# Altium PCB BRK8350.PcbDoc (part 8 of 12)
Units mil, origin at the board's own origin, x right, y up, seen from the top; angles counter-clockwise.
Board outline 9448.82 x 5905.51 mil, 8 copper layers (L1-TOP, L2-GND, L3-SIG, L4-GND, L5-PWR, L6-PWR, L7-GND, L8-BOT), stack 57.69 mil thick; 288 components, 543 nets, 1891 pads, 2032 vias.
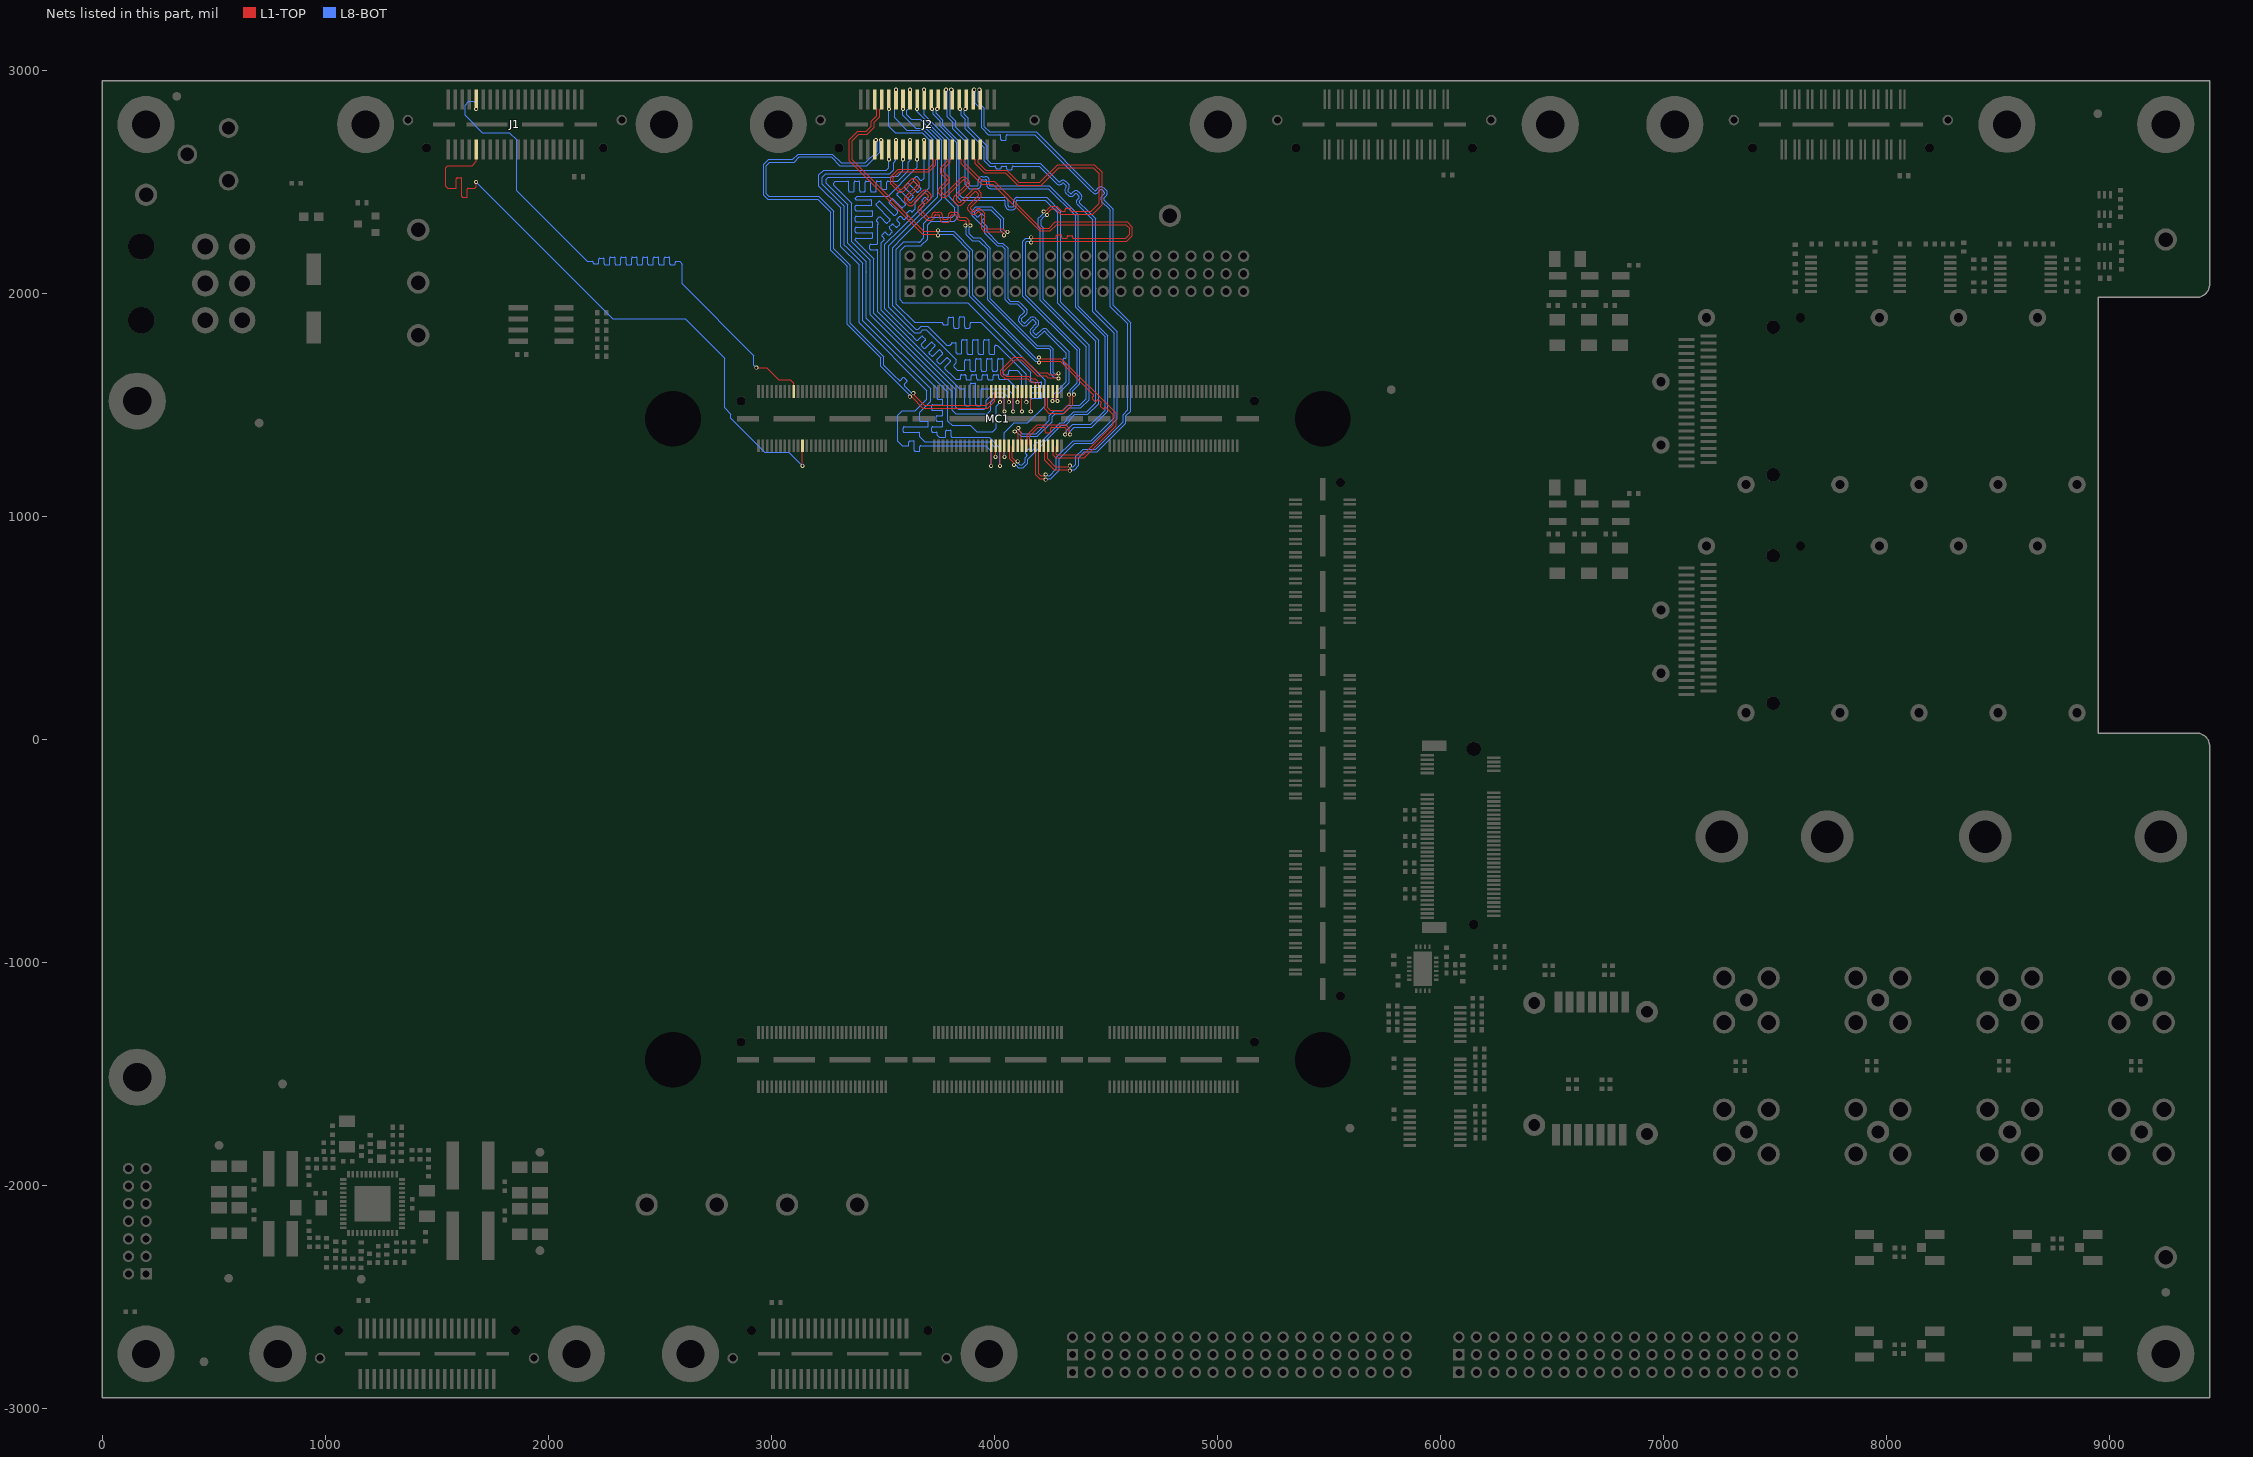
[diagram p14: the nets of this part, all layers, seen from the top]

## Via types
v1: diameter 18, hole 10, L1-TOP to L8-BOT, tented both sides, 2032 vias

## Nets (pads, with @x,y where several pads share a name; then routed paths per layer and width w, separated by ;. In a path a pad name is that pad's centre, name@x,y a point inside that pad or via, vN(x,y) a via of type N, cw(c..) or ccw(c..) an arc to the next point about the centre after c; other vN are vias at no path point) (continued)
PORTC_S26: J1.31 MC1.17 | length 2790.1
  L1-TOP w4.5: v1(2933.07,1665.35) 2978.96,1665.35 3032.81,1611.5 3085.36,1611.5 3100.41,1596.46 MC1.17@3100.41,1558.68
  L8-BOT w4.5: v1(1677.14,2825.35) 1677.14,2848.59 1666.48,2859.25 1644.69,2859.25 1626.97,2841.54 1626.97,2797.24 1705.16,2719.05 1826.22,2719.05 1858.5,2686.78 1858.5,2458.35 2175.12,2141.73 2182.98,2141.73 2197.29,2141.73 cw(c2197.29,2136.83) 2202.19,2136.83 ccw(c2207.09,2136.83) 2207.09,2131.93 2221.79,2131.93 ccw(c2221.79,2136.83) 2226.69,2136.83 2226.69,2151.87 cw(c2231.59,2151.87) 2231.59,2156.77 2246.29,2156.77 cw(c2246.29,2151.87) 2251.19,2151.87 2251.19,2130.99 ccw(c2256.09,2130.99) 2256.09,2126.09 2270.79,2126.09 ccw(c2270.79,2130.99) 2275.69,2130.99 2275.69,2156.75 cw(c2280.59,2156.75) 2280.59,2161.65 2295.29,2161.65 cw(c2295.29,2156.75) 2300.19,2156.75 2300.19,2130.99 ccw(c2305.09,2130.99) 2305.09,2126.09 2319.79,2126.09 ccw(c2319.79,2130.99) 2324.69,2130.99 2324.69,2156.75 cw(c2329.59,2156.75) 2329.59,2161.65 2344.29,2161.65 cw(c2344.29,2156.75) 2349.19,2156.75 2349.19,2130.99 ccw(c2354.09,2130.99) 2354.09,2126.09 2368.79,2126.09 ccw(c2368.79,2130.99) 2373.69,2130.99 2373.69,2156.75 cw(c2378.59,2156.75) 2378.59,2161.65 2393.29,2161.65 cw(c2393.29,2156.75) 2398.19,2156.75 2398.19,2130.99 ccw(c2403.09,2130.99) 2403.09,2126.09 2417.79,2126.09 ccw(c2417.79,2130.99) 2422.69,2130.99 2422.69,2156.75 cw(c2427.59,2156.75) 2427.59,2161.65 2442.29,2161.65 cw(c2442.29,2156.75) 2447.19,2156.75 2447.19,2130.99 ccw(c2452.09,2130.99) 2452.09,2126.09 2466.79,2126.09 ccw(c2466.79,2130.99) 2471.69,2130.99 2471.69,2156.75 cw(c2476.59,2156.75) 2476.59,2161.65 2491.29,2161.65 cw(c2491.29,2156.75) 2496.19,2156.75 2496.19,2130.99 ccw(c2501.09,2130.99) 2501.09,2126.09 2515.79,2126.09 ccw(c2515.79,2130.99) 2520.69,2130.99 2520.69,2156.75 cw(c2525.59,2156.75) 2525.59,2161.65 2540.29,2161.65 cw(c2540.29,2156.75) 2545.19,2156.75 2545.19,2130.99 ccw(c2550.09,2130.99) 2550.09,2126.09 2564.79,2126.09 ccw(c2564.79,2130.99) 2569.69,2130.99 2569.69,2136.83 cw(c2574.59,2136.83) 2574.59,2141.73 2576.84,2141.73 2589.57,2141.73 2601.38,2129.92 2601.38,2040.78 2922.49,1719.67 2922.49,1675.94 v1(2933.07,1665.35)
PORTC_S27: J1.32 MC1.22 | length 2833.7
  L1-TOP w4.5: v1(1677.14,2497.41) 1677.14,2476.36 1670.28,2469.49 1644.68,2469.49 1642.43,2469.49 ccw(c1642.43,2464.59) 1637.53,2464.59 1637.53,2433.62 cw(c1632.63,2433.62) 1632.63,2428.72 1617.93,2428.72 cw(c1617.93,2433.62) 1613.03,2433.62 1613.03,2512.09 ccw(c1608.13,2512.09) 1608.13,2516.99 1593.43,2516.99 ccw(c1593.43,2512.09) 1588.53,2512.09 1588.53,2474.39 cw(c1583.63,2474.39) 1583.63,2469.49 1553.18,2469.49 1550.2,2469.49 1540.47,2479.22 1540.47,2561.89 1550.43,2571.85 1658.46,2571.85 1677.19,2590.58 J1.32@1677.19,2643.11 ; v1(3139.61,1225.72) 3139.78,1225.88 MC1.22@3139.78,1315.37 MC1.22@3139.94,1315.53
  L8-BOT w4.5: v1(1677.14,2497.41) 2289.49,1885.07 2614.93,1885.07 2791.34,1708.66 2791.34,1484.83 2819.19,1456.98 2819.19,1438.06 2969.84,1287.4 3077.93,1287.4 v1(3139.61,1225.72)
PORTD_C2P_CLKN: J2.36 MC1.89 | length 2523.8
  L1-TOP w4.2: v1(3620.93,1535.35) 3621.89,1534.4 3628.89,1534.4 3679.82,1483.46 3970.06,1483.46 4002.38,1515.78 4002.38,1555.13 MC1.89@4005.92,1558.68
  L8-BOT w4.2: v1(3468.85,2686.46) 3468.85,2682.73 3474.09,2677.49 3474.09,2635.55 3422,2583.47 3313.12,2583.47 3273.75,2622.84 3120.83,2622.84 3097.21,2599.21 2988.01,2599.21 2965.59,2576.79 2965.59,2439.5 2983.83,2421.26 3208.66,2421.26 3267.72,2362.2 3267.72,2192.91 3341.18,2119.45 3341.18,1859.39 3491.34,1709.23 3491.34,1671.95 3540.3,1622.98 3618.29,1544.99 3618.29,1537.99 v1(3620.93,1535.35)
PORTD_C2P_CLKP: J2.34 MC1.87 | length 2523.8
  L1-TOP w4.2: v1(3636.84,1551.26) 3637.8,1550.31 3637.8,1543.31 3685.04,1496.06 3964.85,1496.06 3989.78,1521 3989.78,1555.13 MC1.87@3986.24,1558.68
  L8-BOT w4.2: v1(3491.92,2686.46) 3491.92,2682.73 3486.69,2677.49 3486.69,2630.33 3427.22,2570.87 3307.9,2570.87 3268.53,2610.24 3126.05,2610.24 3102.43,2586.61 2993.23,2586.61 2978.19,2571.57 2978.19,2444.72 2989.04,2433.86 3213.88,2433.86 3280.32,2367.42 3280.32,2198.13 3353.78,2124.67 3353.78,1864.61 3503.94,1714.45 3503.94,1677.17 3549.21,1631.89 3572.7,1608.41 ccw(c3576.12,1611.83) 3579.54,1608.41 3590.4,1619.26 cw(c3593.82,1615.84) 3597.24,1619.26 3607.51,1609 cw(c3604.09,1605.57) 3607.51,1602.15 3596.65,1591.29 ccw(c3600.08,1587.87) 3596.65,1584.45 3615.25,1565.85 3627.2,1553.9 3634.2,1553.9 v1(3636.84,1551.26)
PORTD_P2C_CLKN: J2.35 MC1.118 | length 2571.4
  L1-TOP w4.2: J2.35@3464.59,2868.71 3464.59,2831.96 3470.49,2826.06 3471.58,2826.06 3474.04,2823.6 3474.04,2796.02 3448.79,2770.77 3448.79,2748.18 3425.3,2724.69 3387.84,2724.69 3350.39,2687.25 3350.39,2592.42 3679.03,2263.78 3739.35,2263.78 3744.3,2258.83 v1(3748.03,2258.83) ; v1(4200.79,1688.63) 4203.03,1688.63 4207.98,1693.58 4294.61,1693.58 4425.68,1562.51 4444.28,1543.91 cw(c4440.86,1540.49) 4444.28,1537.06 4440.02,1532.8 ccw(c4443.44,1529.38) 4440.02,1525.96 4450.29,1515.69 ccw(c4453.71,1519.11) 4457.13,1515.69 4461.39,1519.95 cw(c4464.82,1516.53) 4468.24,1519.95 4478.51,1509.68 cw(c4475.08,1506.26) 4478.51,1502.84 4475.9,1500.24 ccw(c4479.33,1496.82) 4475.9,1493.39 4486.17,1483.13 ccw(c4489.59,1486.55) 4493.02,1483.13 4495.62,1485.73 cw(c4499.04,1482.3) 4502.46,1485.73 4520.77,1467.42 4533.03,1455.16 4533.03,1409.98 4397.86,1274.81 4280.43,1274.81 4277.97,1277.27 4277.97,1311.83 MC1.118@4281.51,1315.37
  L8-BOT w4.2: v1(3748.03,2258.83) 3751.77,2258.83 3756.72,2263.78 3812.8,2263.78 3890.96,2185.62 3890.96,2073.07 3890.96,1985.68 4182.73,1693.91 4191.77,1693.91 4197.05,1688.63 v1(4200.79,1688.63)
PORTD_P2C_CLKP: J2.33 MC1.116 | length 2571.3
  L1-TOP w4.2: J2.33@3496.09,2868.71 3496.09,2831.96 3490.19,2826.06 3489.1,2826.06 3486.64,2823.6 3486.64,2790.8 3461.39,2765.55 3461.39,2742.96 3430.52,2712.09 3393.06,2712.09 3362.99,2682.03 3362.99,2597.64 3684.25,2276.38 3739.35,2276.38 3744.3,2281.33 v1(3748.03,2281.33) ; v1(4200.79,1711.13) 4203.03,1711.13 4207.98,1706.18 4299.82,1706.18 4545.63,1460.38 4545.63,1404.76 4403.08,1262.21 4275.21,1262.21 4265.37,1272.05 4265.37,1311.83 MC1.116@4261.83,1315.37
  L8-BOT w4.2: v1(3748.03,2281.33) 3751.77,2281.33 3756.72,2276.38 3818.01,2276.38 3903.56,2190.84 3903.56,2067.85 3903.56,1990.9 4187.95,1706.51 4192.43,1706.51 4197.05,1711.13 v1(4200.79,1711.13)
PORTD_S0_D0P: J2.5 MC1.112 | length 2525.9
  L1-TOP w4.2: MC1.112@4222.46,1315.37 4226,1311.83 4226,1251.32 4268.66,1208.66 4330.71,1208.66 4335.66,1203.71 v1(4338.58,1203.71)
  L8-BOT w4.2: v1(3932.92,2912.06) 3932.92,2908.33 3927.69,2903.09 3927.69,2857.18 3955.54,2829.33 3955.54,2745.34 3978.61,2722.27 4187.18,2722.27 4443.29,2466.16 4449.23,2460.22 ccw(c4452.65,2463.64) 4456.07,2460.22 4467.06,2471.21 cw(c4479.4,2458.88) 4489.55,2473.06 4489.88,2473.06 4491.7,2471.23 4502,2460.94 4503.84,2459.1 4503.84,2458.77 cw(c4489.66,2448.61) 4502,2436.28 4491,2425.29 ccw(c4494.43,2421.87) 4491,2418.44 4520.88,2388.57 4533.48,2375.97 4533.48,1944.97 4611.03,1867.42 4611.03,1471.16 4590.03,1450.16 4590.03,1417.07 4460.97,1288 4403.99,1288 4378.19,1262.21 4378.19,1227.31 4359.55,1208.66 4347.27,1208.66 4342.32,1203.71 v1(4338.58,1203.71)
PORTD_S1_D1P: J2.6 MC1.100 | length 2569.2
  L1-TOP w4.2: J2.6@3937.09,2643.11 3937.09,2606.36 3931.19,2600.46 3930.1,2600.46 3927.64,2598 3927.64,2584.17 3960.63,2551.18 4055.12,2551.18 4110.24,2496.06 4204.72,2496.06 4284.25,2575.59 4449.1,2575.59 4483.63,2541.07 4483.63,2396.77 4440.4,2353.54 4374.02,2353.54 4297.52,2353.54 4273.9,2377.16 4257.7,2377.16 4244.39,2363.86 4239.72,2359.18 4239.72,2352.18 v1(4237.08,2349.54) ; v1(4091.61,1379.3) 4093.7,1377.21 4100.7,1377.21 4107.89,1370.02 4107.89,1318.91 MC1.100@4104.35,1315.37
  L8-BOT w4.2: v1(4091.61,1379.3) 4094.26,1376.66 4101.26,1376.66 4120.43,1357.48 4193.41,1357.48 4259.84,1423.91 4259.84,1444.98 4273.56,1458.7 4309.49,1458.7 4335.58,1484.79 4388.44,1484.79 4425.56,1521.91 4425.56,1633.42 4425.56,1765.21 4218.36,1972.4 4218.36,1988.96 4218.52,1989.11 4218.52,2216.54 4218.52,2293.68 4210.24,2301.96 4210.24,2329.7 4222.08,2341.55 4227.43,2346.9 4234.44,2346.9 v1(4237.08,2349.54)
PORTD_S2_D0N: J2.7 MC1.114 | length 2525.7
  L1-TOP w4.2: MC1.114@4242.14,1315.37 4238.6,1311.83 4238.6,1256.54 4273.88,1221.26 4330.71,1221.26 4335.66,1226.21 v1(4338.58,1226.21)
  L8-BOT w4.2: v1(3909.85,2912.06) 3909.85,2908.33 3915.09,2903.09 3915.09,2851.96 3942.94,2824.11 3942.94,2740.12 3973.39,2709.67 3995.72,2709.67 4024.38,2709.67 cw(c4024.38,2704.83) 4029.22,2704.83 4029.22,2689.48 ccw(c4034.06,2689.48) 4034.06,2684.64 4048.58,2684.64 ccw(c4048.58,2689.48) 4053.42,2689.48 4053.42,2704.83 cw(c4058.26,2704.83) 4058.26,2709.67 4060.36,2709.67 4181.96,2709.67 4434.38,2457.25 4440.32,2451.31 ccw(c4452.65,2463.64) 4464.98,2451.31 4475.97,2462.3 cw(c4479.4,2458.88) 4482.84,2462.28 ; v1(4338.58,1226.21) 4342.32,1226.21 4347.27,1221.26 4354.33,1221.26 4365.59,1232.53 4365.59,1267.43 4398.77,1300.6 4455.75,1300.6 4577.43,1422.29 4577.43,1455.38 4598.43,1476.38 4598.43,1862.2 4520.88,1939.75 4520.88,2370.75 4511.97,2379.66 4482.1,2409.53 cw(c4494.43,2421.87) 4482.1,2434.2 4493.09,2445.19 ccw(c4489.66,2448.61) 4493.07,2452.05 4482.85,2462.27
PORTD_S3_D1N: J2.8 MC1.102 | length 2569.2
  L1-TOP w4.2: J2.8@3905.59,2643.11 3905.59,2606.36 3911.49,2600.46 3912.58,2600.46 3915.04,2598 3915.04,2578.95 3955.41,2538.58 4049.9,2538.58 4105.02,2483.46 4209.94,2483.46 4289.47,2562.99 4443.88,2562.99 4471.03,2535.85 4471.03,2401.99 4435.18,2366.14 4374.02,2366.14 4347.89,2366.14 cw(c4347.89,2370.98) 4343.05,2370.98 4343.05,2375.89 ccw(c4338.21,2375.89) 4338.21,2380.73 4323.69,2380.73 ccw(c4323.69,2375.89) 4318.85,2375.89 4318.85,2370.98 cw(c4314.01,2370.98) 4314.01,2366.14 4311.91,2366.14 4302.74,2366.14 4279.12,2389.76 4252.48,2389.76 4239.18,2376.46 4230.81,2368.09 4223.81,2368.09 v1(4221.17,2365.45) ; v1(4107.52,1395.21) 4109.61,1393.12 4109.61,1386.12 4120.49,1375.24 4120.49,1318.91 MC1.102@4124.03,1315.37
  L8-BOT w4.2: v1(4107.52,1395.21) 4110.17,1392.57 4110.17,1385.57 4125.65,1370.08 4188.19,1370.08 4247.24,1429.13 4247.24,1450.2 4268.34,1471.3 4304.27,1471.3 4330.36,1497.39 4383.22,1497.39 4412.96,1527.13 4412.96,1633.42 4412.96,1759.99 4205.76,1967.18 4205.76,1994.18 4205.92,1994.33 4205.92,2216.54 4205.92,2288.46 4197.64,2296.74 4197.64,2334.92 4209.48,2346.76 4218.53,2355.81 4218.53,2362.81 v1(4221.17,2365.45)
PORTD_S4_D2P: J2.9 MC1.108 | length 2525.7
  L1-TOP w4.2: MC1.108@4183.09,1315.37 4186.63,1311.83 4186.63,1185.32 4203.44,1168.5 4224.41,1168.5 4229.36,1163.55 v1(4230.43,1163.55)
  L8-BOT w4.2: v1(3869.82,2825.35) 3869.82,2821.61 3864.59,2816.38 3864.59,2801.72 3882.62,2783.69 3882.62,2742.52 3967.5,2657.63 3967.5,2598.41 3984.24,2581.67 4205.73,2581.67 4237.7,2549.7 4288.1,2499.3 ccw(c4291.52,2502.73) 4294.94,2499.3 4296.01,2500.37 cw(c4308.35,2488.04) 4318.5,2502.22 4318.83,2502.22 4320.65,2500.4 ; v1(4230.43,1163.55) 4234.16,1163.55 4239.11,1168.5 4253.46,1168.5 4291.34,1206.38 4291.34,1257.77 4359.55,1325.98 4440.08,1325.98 4522.42,1408.32 4522.79,1408.32 4551.18,1436.72 4551.18,1635.53 4551.26,1635.61 4551.26,1648.18 4551.26,1825.85 4454.55,1922.55 4454.55,1995.14 4454.74,1995.32 4454.74,2020.43 4454.55,2020.61 4454.55,2073.88 4454.74,2074.06 4454.74,2099.17 4454.55,2099.35 4454.55,2152.62 4454.74,2152.8 4454.74,2177.91 4454.55,2178.09 4454.55,2332.85 4413.88,2373.52 4381.92,2405.49 cw(c4385.34,2408.91) 4381.92,2412.33 4388.12,2418.54 ; 4320.68,2500.37 4330.94,2490.11 ; 4330.97,2490.08 4332.79,2488.26 4332.79,2487.93 cw(c4318.61,2477.78) 4330.94,2465.44 4329.87,2464.37 ccw(c4333.3,2460.95) 4329.87,2457.53 4340.14,2447.26 ccw(c4343.56,2450.68) 4346.96,2447.24 4353.22,2453.49 cw(c4365.55,2441.16) 4375.71,2455.34 4376.04,2455.34 4377.86,2453.52 ; 4377.88,2453.49 4388.15,2443.23 4390,2441.38 4390,2441.05 cw(c4375.82,2430.9) 4388.15,2418.56
PORTD_S5_D3P: J2.10 MC1.111 | length 2569.1
  L1-TOP w4.2: J2.10@3874.09,2643.11 3874.09,2606.36 3868.19,2600.46 3867.1,2600.46 3864.64,2598 3864.64,2584.18 3896.65,2552.17 3948.03,2500.79 3998.93,2500.79 4208.38,2291.34 4245.96,2291.34 4274.31,2319.69 4595.29,2319.69 4619.42,2295.55 4619.42,2257.56 4594.15,2232.28 4381.89,2232.28 4174.06,2232.28 4169.11,2227.33 v1(4165.38,2227.33) ; MC1.111@4222.46,1558.68 4226,1555.13 4226,1480.47 4244.55,1461.91 4314.38,1461.91 4352.17,1499.7 4352.17,1535.61 4357.12,1540.56 v1(4357.12,1544.29)
  L8-BOT w4.2: v1(4165.38,2227.33) 4161.64,2227.33 4156.69,2232.28 4146.33,2232.28 4140.34,2226.29 4140.34,1991.17 4383.66,1747.85 4383.66,1593.34 4352.17,1561.85 4352.17,1552.98 4357.12,1548.03 v1(4357.12,1544.29)
PORTD_S6_D2N: J2.11 MC1.110 | length 2525.3
  L1-TOP w4.2: MC1.110@4202.77,1315.37 4199.23,1311.83 4199.23,1190.53 4208.66,1181.1 4224.41,1181.1 4229.36,1186.05 v1(4230.43,1186.05)
  L8-BOT w4.2: v1(3846.75,2825.35) 3846.75,2821.61 3851.99,2816.38 3851.99,2796.5 3870.02,2778.47 3870.02,2737.3 3954.9,2652.42 3954.9,2593.19 3979.02,2569.07 3988.78,2569.07 4002.23,2569.07 cw(c4002.23,2564.23) 4007.07,2564.23 4007.07,2561.62 ccw(c4011.91,2561.62) 4011.91,2556.78 4026.43,2556.78 ccw(c4026.43,2561.62) 4031.27,2561.62 4031.27,2564.23 cw(c4036.11,2564.23) 4036.11,2569.07 4050.63,2569.07 cw(c4050.63,2564.23) 4055.47,2564.23 4055.47,2557.01 ccw(c4060.31,2557.01) 4060.31,2552.17 4074.83,2552.17 ccw(c4074.83,2557.01) 4079.67,2557.01 4079.67,2564.23 cw(c4084.51,2564.23) 4084.51,2569.07 4086.61,2569.07 4200.51,2569.07 4228.79,2540.8 4279.19,2490.39 ccw(c4291.52,2502.73) 4303.85,2490.39 4304.92,2491.46 cw(c4308.35,2488.04) 4311.79,2491.45 ; v1(4230.43,1186.05) 4234.16,1186.05 4239.11,1181.1 4248.25,1181.1 4278.74,1211.6 4278.74,1262.99 4354.33,1338.58 4434.86,1338.58 4517.2,1420.92 4517.57,1420.92 4538.58,1441.94 4538.58,1641.82 4538.63,1641.87 4538.63,1648.16 ; 4311.8,2491.43 4322,2481.23 cw(c4318.61,2477.78) 4322.04,2474.35 4320.96,2473.28 ccw(c4333.3,2460.95) 4320.96,2448.62 4331.23,2438.35 ccw(c4343.56,2450.68) 4355.9,2438.35 4362.13,2444.59 cw(c4365.55,2441.16) 4368.99,2444.57 4379.21,2434.35 ; 4379.22,2434.34 cw(c4375.82,2430.9) 4379.26,2427.5 4373.01,2421.24 ccw(c4385.34,2408.91) 4373.01,2396.58 4404.97,2364.61 4441.95,2327.63 4441.95,2171.88 4442.14,2171.7 4442.14,2159.01 4441.95,2158.82 4441.95,2093.14 4442.14,2092.96 4442.14,2080.27 4441.95,2080.08 4441.95,2014.4 4442.14,2014.22 4442.14,2001.53 4441.95,2001.34 4441.95,1917.33 4538.66,1820.63 4538.66,1648.18
PORTD_S7_D3N: J2.12 MC1.113 | length 2569.1
  L1-TOP w4.2: J2.12@3842.59,2643.11 3842.59,2606.36 3848.49,2600.46 3849.58,2600.46 3852.04,2598 3852.04,2578.96 3878.83,2552.17 3942.81,2488.19 3993.71,2488.19 4203.16,2278.74 4251.18,2278.74 4279.53,2307.09 4590.07,2307.09 4606.82,2290.33 4606.82,2262.78 4588.93,2244.88 4381.89,2244.88 4356.03,2244.88 cw(c4356.03,2249.72) 4351.19,2249.72 4351.19,2253.12 ccw(c4346.35,2253.12) 4346.35,2257.96 4331.83,2257.96 ccw(c4331.83,2253.12) 4326.99,2253.12 4326.99,2249.72 cw(c4322.15,2249.72) 4322.15,2244.88 4307.63,2244.88 cw(c4307.63,2249.72) 4302.79,2249.72 4302.79,2256.15 ccw(c4297.95,2256.15) 4297.95,2260.99 4283.43,2260.99 ccw(c4283.43,2256.15) 4278.59,2256.15 4278.59,2249.72 cw(c4273.75,2249.72) 4273.75,2244.88 4271.65,2244.88 4174.06,2244.88 4169.11,2249.83 v1(4165.38,2249.83) ; MC1.113@4242.14,1558.68 4238.6,1555.13 4238.6,1485.69 4249.77,1474.51 4309.16,1474.51 4339.57,1504.92 4339.57,1535.61 4334.62,1540.56 v1(4334.62,1544.29)
  L8-BOT w4.2: v1(4165.38,2249.83) 4161.64,2249.83 4156.69,2244.88 4141.11,2244.88 4127.74,2231.51 4127.74,1985.95 4371.06,1742.63 4371.06,1598.56 4339.57,1567.07 4339.57,1552.98 4334.62,1548.03 v1(4334.62,1544.29)
PORTD_S8_D4P: J2.13 MC1.104 | length 2525.8
  L1-TOP w4.2: MC1.104@4143.72,1315.37 4147.26,1318.91 4147.26,1365.87 4191.63,1410.24 4320.18,1410.24 4335.43,1394.98 4335.43,1374.02 4340.38,1369.07 v1(4340.38,1366.14)
  L8-BOT w4.2: v1(3806.92,2912.06) 3806.92,2908.33 3801.69,2903.09 3801.69,2795.72 3826.51,2770.89 3826.51,2742.52 3882.68,2686.36 3882.68,2491.34 3892.74,2481.27 3915.14,2481.27 3923.54,2481.27 ccw(c3923.54,2486.11) 3928.38,2486.11 3928.38,2504.24 cw(c3945.82,2504.24) 3945.82,2521.68 3960.34,2521.68 cw(c3960.34,2504.24) 3977.78,2504.24 3977.78,2486.11 ccw(c3982.62,2486.11) 3982.62,2481.27 4050.41,2481.27 4247.01,2481.27 4376.8,2351.49 4376.8,2171.59 4376.76,2171.55 4376.76,2159.15 4376.8,2159.11 4376.8,2092.85 4376.76,2092.81 4376.76,2080.41 4376.8,2080.37 4376.8,2014.11 4376.76,2014.07 4376.76,2001.67 4376.8,2001.63 4376.8,1941.05 4509.36,1808.49 4509.36,1636.66 4509.36,1470.52 4437.71,1398.87 4357.32,1398.87 4337.43,1378.98 4337.43,1375.5 4337.74,1375.19 4337.74,1368.78 v1(4340.38,1366.14)
PORTD_S9_D5P: J2.14 MC1.115 | length 2573
  L1-TOP w4.2: 3795.79,2519.06 3772.44,2542.4 3772.44,2551.97 3772.44,2557.64 3801.64,2586.84 3801.64,2598 3804.1,2600.46 3805.19,2600.46 3811.09,2606.36 J2.14@3811.09,2643.11 ; 3795.81,2519.03 3797.63,2517.21 3797.63,2516.88 cw(c3783.45,2506.72) 3795.79,2494.39 3761.47,2460.07 ccw(c3764.89,2456.65) 3761.47,2453.23 3771.73,2442.96 ccw(c3775.16,2446.38) 3778.55,2442.94 3850.33,2514.71 cw(c3862.66,2502.38) 3872.82,2516.56 3873.15,2516.56 3874.97,2514.73 ; 3874.99,2514.71 3885.26,2504.44 3887.11,2502.6 3887.11,2502.27 cw(c3872.93,2492.11) 3885.26,2479.78 ; 3885.23,2479.75 3830.31,2424.83 ccw(c3833.73,2421.4) 3830.31,2417.98 3840.57,2407.71 ccw(c3844,2411.14) 3847.4,2407.69 3902.37,2462.67 cw(c3914.7,2450.34) 3924.86,2464.51 3925.19,2464.51 3927.01,2462.69 3937.3,2452.4 ; 3937.28,2427.71 3893.62,2384.05 ccw(c3897.04,2380.63) 3893.62,2377.21 3903.89,2366.94 ccw(c3907.31,2370.37) 3910.71,2366.92 3916.98,2373.19 cw(c3929.32,2360.86) 3939.47,2375.04 3939.8,2375.04 3941.63,2373.22 ; 3937.3,2427.74 ccw(c3924.97,2440.07) 3939.15,2450.23 3939.15,2450.56 3937.33,2452.38 ; 3941.65,2373.19 3947.59,2367.25 3956.5,2358.35 3956.5,2292.61 3960.92,2288.19 4038.58,2288.19 4049.5,2277.28 4056.5,2277.28 v1(4059.14,2274.64) ; v1(4260.42,1515.75) 4260.42,1518.88 4265.37,1523.83 4265.37,1555.13 MC1.115@4261.83,1558.68
  L8-BOT w4.2: v1(4059.14,2274.64) 4058.18,2275.59 4051.18,2275.59 4041.94,2284.84 4041.94,2334.15 3989.08,2387 3917.64,2387 3899.98,2369.34 3899.98,2346.77 3956.08,2290.67 3956.08,2269.2 4013.47,2211.81 4032.53,2211.81 4048.97,2195.37 4048.97,1969.45 4066.7,1951.72 4102.86,1951.72 4109.76,1944.82 4133.92,1920.66 ; 4133.93,1920.64 cw(c4130.53,1917.2) 4133.95,1913.78 4112.91,1892.73 ccw(c4125.24,1880.4) 4112.91,1868.07 4123.17,1857.8 ccw(c4135.51,1870.13) 4147.84,1857.8 ; 4147.86,1857.82 4168.88,1878.85 cw(c4172.31,1875.42) 4175.75,1878.83 4185.96,1868.61 cw(c4182.57,1865.16) 4186.02,1861.76 4164.95,1840.69 ccw(c4177.28,1828.36) 4164.95,1816.02 4175.22,1805.76 ccw(c4187.55,1818.09) 4199.88,1805.76 ; 4199.91,1805.78 4220.93,1826.8 cw(c4224.35,1823.38) 4227.79,1826.78 ; 4227.81,1826.77 4233.71,1820.86 4323.57,1731.01 4323.57,1724.96 4323.57,1713.15 cw(c4318.73,1713.15) 4318.73,1708.31 4313.81,1708.31 ccw(c4313.81,1703.47) 4308.97,1703.47 4308.97,1688.95 ccw(c4313.81,1688.95) 4313.81,1684.11 4318.73,1684.11 cw(c4318.73,1679.27) 4323.57,1679.27 4323.57,1677.17 4323.57,1603.23 4265.37,1545.03 4265.37,1524.43 4260.42,1519.48 v1(4260.42,1515.75)
PORTD_S10_D4N: J2.15 MC1.106 | length 2525
  L1-TOP w4.2: MC1.106@4163.4,1315.37 4159.86,1318.91 4159.86,1360.65 4196.85,1397.64 4223.15,1397.64 cw(c4223.15,1392.8) 4227.99,1392.8 4227.99,1378.7 ccw(c4232.83,1378.7) 4232.83,1373.86 4247.35,1373.86 ccw(c4247.35,1378.7) 4252.19,1378.7 4252.19,1392.8 cw(c4257.03,1392.8) 4257.03,1397.64 4291.34,1397.64 4314.96,1397.64 4322.83,1389.76 4322.83,1374.02 4317.88,1369.07 v1(4317.88,1366.14)
  L8-BOT w4.2: v1(3783.85,2912.06) 3783.85,2908.33 3789.09,2903.09 3789.09,2790.5 3813.91,2765.67 3813.91,2737.3 3870.08,2681.14 3870.08,2486.12 3887.52,2468.67 3915.14,2468.67 3923.54,2468.67 ccw(c3923.54,2486.11) 3940.98,2486.11 3940.98,2504.24 cw(c3945.82,2504.24) 3945.82,2509.08 3960.34,2509.08 cw(c3960.34,2504.24) 3965.18,2504.24 3965.18,2486.11 ccw(c3982.62,2486.11) 3982.62,2468.67 4050.41,2468.67 4241.79,2468.67 4364.2,2346.27 4364.2,2176.81 4364.16,2176.77 4364.16,2153.94 4364.2,2153.9 4364.2,2098.07 4364.16,2098.03 4364.16,2075.2 4364.2,2075.16 4364.2,2019.33 4364.16,2019.29 4364.16,1996.46 4364.2,1996.41 4364.2,1935.83 4496.76,1803.27 4496.76,1631.42 4496.76,1475.73 4432.49,1411.47 4352.1,1411.47 4324.83,1384.2 4324.83,1374.89 4317.88,1367.94 v1(4317.88,1366.14)
PORTD_S11_D5N: J2.16 MC1.117 | length 2572.8
  L1-TOP w4.2: J2.16@3779.59,2643.11 3779.59,2606.36 3785.49,2600.46 3786.58,2600.46 3789.04,2598 3789.04,2592.06 3759.84,2562.86 3759.84,2539.37 3759.84,2537.18 3786.84,2510.18 cw(c3783.45,2506.72) 3786.88,2503.3 3752.56,2468.98 ccw(c3764.89,2456.65) 3752.56,2444.32 3762.82,2434.05 ccw(c3775.16,2446.38) 3787.49,2434.05 ; 3787.51,2434.07 3859.24,2505.8 cw(c3862.66,2502.38) 3866.1,2505.78 3876.32,2495.57 cw(c3872.93,2492.11) 3876.37,2488.71 3821.4,2433.74 ccw(c3833.73,2421.4) 3821.4,2409.07 3831.66,2398.8 ccw(c3844,2411.14) 3856.33,2398.8 ; 3856.35,2398.83 3911.28,2453.76 cw(c3914.7,2450.34) 3918.15,2453.74 3928.36,2443.52 cw(c3924.97,2440.07) 3928.42,2436.67 3884.71,2392.96 ccw(c3897.04,2380.63) 3884.71,2368.3 3894.98,2358.03 ccw(c3907.31,2370.37) 3919.64,2358.03 ; 3919.67,2358.06 3925.89,2364.29 cw(c3929.32,2360.86) 3932.76,2364.27 3938.68,2358.35 3943.9,2353.13 3943.9,2287.39 3955.7,2275.59 4033.36,2275.59 4040.59,2268.37 4040.59,2261.37 v1(4043.23,2258.73) ; MC1.117@4281.51,1558.68 4277.97,1555.13 4277.97,1523.83 4282.92,1518.88 v1(4282.92,1515.75)
  L8-BOT w4.2: v1(4043.23,2258.73) 4042.27,2259.68 4042.27,2266.68 4029.34,2279.62 4029.34,2328.93 3983.86,2374.4 3922.86,2374.4 3912.58,2364.12 3912.58,2351.99 3914.01,2350.57 3921.29,2343.28 ccw(c3924.71,2346.7) 3928.14,2343.28 3938.97,2354.11 cw(c3942.39,2350.69) 3945.81,2354.11 3956.08,2343.85 cw(c3952.66,2340.42) 3956.08,2337 3945.25,2326.17 ccw(c3948.67,2322.75) 3945.25,2319.32 3963.85,2300.73 3968.68,2295.89 3968.68,2274.42 4018.69,2224.41 4037.75,2224.41 4061.57,2200.59 4061.57,1974.67 4071.92,1964.32 4108.07,1964.32 4118.67,1953.72 4142.86,1929.53 4144.71,1927.69 4144.71,1927.36 cw(c4130.53,1917.2) 4142.86,1904.87 4121.82,1883.82 ccw(c4125.24,1880.4) 4121.82,1876.98 4132.08,1866.71 ccw(c4135.51,1870.13) 4138.9,1866.69 4159.97,1887.76 cw(c4172.31,1875.42) 4182.46,1889.6 4182.79,1889.6 4184.62,1887.78 4194.91,1877.49 4196.75,1875.64 4196.75,1875.31 cw(c4182.57,1865.16) 4194.91,1852.82 ; 4194.88,1852.8 4173.86,1831.78 ccw(c4177.28,1828.36) 4173.86,1824.93 4184.13,1814.67 ccw(c4187.55,1818.09) 4190.95,1814.64 4212.02,1835.71 cw(c4224.35,1823.38) 4234.51,1837.56 4234.84,1837.56 4236.66,1835.74 4242.62,1829.77 4336.17,1736.23 4336.17,1598.01 4277.97,1539.82 4277.97,1524.43 4282.92,1519.48 v1(4282.92,1515.75)
PORTD_S12_D6P: J2.17 MC1.96 | length 2525.8
  L1-TOP w4.2: MC1.96@4064.98,1315.37 4068.52,1311.83 4068.52,1257.09 4086.07,1239.54 4086.07,1232.54 v1(4088.71,1229.9)
  L8-BOT w4.2: v1(3743.82,2825.35) 3743.82,2821.61 3738.59,2816.38 3738.59,2806.19 3769.55,2775.23 3769.55,2753.23 3843.31,2679.47 3843.31,2440.16 3854.66,2428.8 4011.81,2428.8 4044.59,2428.8 cw(c4044.59,2411.36) 4062.03,2411.36 4062.03,2391.76 ccw(c4066.87,2391.76) 4066.87,2386.92 4081.39,2386.92 ccw(c4081.39,2391.76) 4086.23,2391.76 4086.23,2411.36 cw(c4103.67,2411.36) 4103.67,2428.8 4112.07,2428.8 4234.72,2428.8 4298.02,2365.51 4298.02,1972.44 4298.02,1958.84 4467.46,1789.4 4467.46,1628.5 4467.46,1503.96 4419.4,1455.9 4361.42,1455.9 4338.45,1432.94 4338.45,1425.05 4319.7,1406.29 4300.77,1406.29 4150.32,1255.84 4150.32,1237.78 4130.03,1217.49 4108.12,1217.49 4098.35,1227.26 4091.35,1227.26 v1(4088.71,1229.9)
PORTD_S13_D7P: J2.18 MC1.107 | length 2572.9
  L1-TOP w4.2: 3649.88,2507.46 3648.06,2509.28 3647.73,2509.28 ccw(c3637.57,2495.11) 3625.24,2507.44 3583.97,2466.18 cw(c3580.55,2469.6) 3577.13,2466.18 3560.16,2483.14 3547.58,2495.73 3547.58,2517.23 3573.66,2543.31 3706.8,2543.31 3737.89,2574.41 3737.89,2597.25 3741.1,2600.46 3742.19,2600.46 3748.09,2606.36 J2.18@3748.09,2643.11 ; 3649.9,2507.44 3660.17,2497.17 3662.01,2495.33 3662.01,2495 cw(c3647.84,2484.84) 3660.17,2472.51 3609.89,2422.23 ccw(c3613.32,2418.81) 3609.89,2415.39 3620.16,2405.12 ccw(c3623.58,2408.55) 3626.98,2405.1 3677.57,2455.69 cw(c3689.91,2443.36) 3700.06,2457.54 3700.39,2457.54 3702.22,2455.71 ; 3702.24,2455.69 3712.51,2445.42 3714.35,2443.58 3714.35,2443.25 cw(c3700.17,2433.09) 3712.51,2420.76 ; 3712.48,2420.73 3670.95,2379.2 ccw(c3674.37,2375.78) 3670.95,2372.36 3702.91,2340.4 3703.94,2339.37 3705.85,2339.37 3714.25,2339.37 ccw(c3714.25,2344.21) 3719.09,2344.21 3719.09,2345.34 cw(c3736.53,2345.34) 3736.53,2362.78 3751.05,2362.78 cw(c3751.05,2345.34) 3768.49,2345.34 3768.49,2334.87 ccw(c3773.33,2334.87) 3773.33,2330.03 3787.85,2330.03 ccw(c3787.85,2334.87) 3792.69,2334.87 3792.69,2345.34 cw(c3810.13,2345.34) 3810.13,2362.78 3824.65,2362.78 cw(c3824.65,2345.34) 3842.09,2345.34 3842.09,2344.21 ccw(c3846.93,2344.21) 3846.93,2339.37 3867.13,2339.37 3872.35,2339.37 3887.6,2324.12 3887.6,2311.83 3892.55,2306.88 v1(3892.55,2303.15) ; MC1.107@4183.09,1558.68 4186.63,1562.22 4186.63,1593.52 4177.88,1602.27 4162.22,1602.27 4149.62,1614.87 4048.43,1614.87 4029.25,1634.05 4029.25,1654.06 4087.78,1712.6 4125.77,1712.6 4196.64,1641.73 4237.67,1641.73 4245.39,1634.02 4277.62,1634.02 4283.68,1640.08 v1(4287.42,1640.08)
  L8-BOT w4.2: v1(3892.55,2303.15) 3892.55,2299.42 3887.6,2294.47 3887.6,2265.91 3906.54,2246.97 3936.5,2246.97 3982.3,2201.17 3982.3,1975.2 4192.93,1764.57 4248.43,1764.57 4264.76,1748.23 4264.76,1678.69 ; 4264.74,1678.66 4264.74,1642.51 4272.12,1635.13 4278.73,1635.13 4283.68,1640.08 v1(4287.42,1640.08)
PORTD_S14_D6N: J2.19 MC1.98 | length 2525.8
  L1-TOP w4.2: MC1.98@4084.66,1315.37 4081.12,1311.83 4081.12,1262.31 4094.97,1248.45 4101.98,1248.45 v1(4104.62,1245.81)
  L8-BOT w4.2: v1(3720.75,2825.35) 3720.75,2821.61 3725.99,2816.38 3725.99,2800.97 3756.95,2770.01 3756.95,2748.01 3830.71,2674.25 3830.71,2434.94 3849.44,2416.2 4011.81,2416.2 4044.59,2416.2 cw(c4044.59,2411.36) 4049.43,2411.36 4049.43,2391.76 ccw(c4066.87,2391.76) 4066.87,2374.32 4081.39,2374.32 ccw(c4081.39,2391.76) 4098.83,2391.76 4098.83,2411.36 cw(c4103.67,2411.36) 4103.67,2416.2 4112.07,2416.2 4229.5,2416.2 4285.42,2360.29 4285.42,1953.62 4454.86,1784.18 4454.86,1628.5 4454.86,1509.18 4414.19,1468.5 4356.2,1468.5 4325.85,1438.16 4325.85,1430.26 4314.48,1418.89 4295.55,1418.89 4210.08,1333.42 4203.38,1326.72 cw(c4199.96,1330.14) 4196.53,1326.72 4194.95,1328.3 ccw(c4191.53,1324.88) 4188.1,1328.3 4177.84,1318.03 ccw(c4181.26,1314.61) 4177.84,1311.19 4179.42,1309.6 cw(c4176,1306.18) 4179.42,1302.76 4169.15,1292.49 cw(c4165.73,1295.92) 4162.31,1292.49 4156.94,1297.86 ccw(c4153.52,1294.44) 4150.1,1297.86 4139.83,1287.59 ccw(c4143.25,1284.17) 4139.83,1280.75 4145.2,1275.38 cw(c4141.78,1271.96) 4145.2,1268.54 4143.71,1267.05 4137.72,1261.06 4137.72,1243 4124.81,1230.09 4113.34,1230.09 4107.26,1236.17 4107.26,1243.17 v1(4104.62,1245.81)
PORTD_S15_D7N: J2.20 MC1.109 | length 2577.9
  L1-TOP w4.2: 3651.24,2488.28 cw(c3647.84,2484.84) 3651.26,2481.42 3600.99,2431.14 ccw(c3613.32,2418.81) 3600.99,2406.48 3611.25,2396.21 ccw(c3623.58,2408.55) 3635.92,2396.21 3686.48,2446.78 cw(c3689.91,2443.36) 3693.35,2446.76 3703.56,2436.55 ; 3651.23,2488.3 3641.02,2498.5 ccw(c3637.57,2495.11) 3634.15,2498.53 3592.88,2457.27 cw(c3580.55,2469.6) 3568.22,2457.27 3551.25,2474.23 3534.98,2490.51 3534.98,2522.45 3568.44,2555.91 3701.58,2555.91 3725.29,2579.63 3725.29,2597.65 3716.59,2606.36 J2.20@3716.59,2643.11 ; 3703.58,2436.53 cw(c3700.17,2433.09) 3703.62,2429.69 3662.04,2388.11 ccw(c3674.37,2375.78) 3662.04,2363.45 3694,2331.49 3698.72,2326.77 3705.85,2326.77 3714.25,2326.77 ccw(c3714.25,2344.21) 3731.69,2344.21 3731.69,2345.34 cw(c3736.53,2345.34) 3736.53,2350.18 3751.05,2350.18 cw(c3751.05,2345.34) 3755.89,2345.34 3755.89,2334.87 ccw(c3773.33,2334.87) 3773.33,2317.43 3787.85,2317.43 ccw(c3787.85,2334.87) 3805.29,2334.87 3805.29,2345.34 cw(c3810.13,2345.34) 3810.13,2350.18 3824.65,2350.18 cw(c3824.65,2345.34) 3829.49,2345.34 3829.49,2344.21 ccw(c3846.93,2344.21) 3846.93,2326.77 3867.13,2326.77 3875,2318.9 3875,2311.83 3870.05,2306.88 v1(3870.05,2303.15) ; MC1.109@4202.77,1558.68 4199.23,1562.22 4199.23,1598.74 4183.1,1614.87 4167.44,1614.87 4154.84,1627.47 4053.65,1627.47 4041.85,1639.27 4041.85,1648.84 4093,1700 4120.55,1700 4191.42,1629.13 4232.45,1629.13 4240.17,1621.41 4278.06,1621.41 4279.25,1620.22 v1@4281.04,1620.22 ; v1@4281.04,1620.22 4284.78,1620.22 v1(4287.42,1617.58) 4283.68,1617.58 v1@4281.04,1620.22
  L8-BOT w4.2: v1(3870.05,2303.15) 3870.05,2299.42 3875,2294.47 3875,2260.69 3901.32,2234.37 3931.28,2234.37 3969.7,2195.95 3969.7,1969.98 4187.71,1751.97 4243.21,1751.97 4252.11,1743.06 4252.11,1678.69 4252.14,1637.29 4266.9,1622.53 4278.73,1622.53 4283.68,1617.58 v1(4287.42,1617.58)
PORTD_S16: J2.21 MC1.94 | length 2521.3
  L1-TOP w4.5: v1(4045.19,1265.77) 4045.29,1265.87 MC1.94@4045.29,1315.37 MC1.94@4045.39,1315.47
  L8-BOT w4.5: v1(3685.04,2912.06) 3685.04,2799.92 3796.98,2687.98 3796.98,2431.77 3838.44,2390.31 3838.44,2341.39 3819.88,2322.83 3716.54,2322.83 3700.79,2307.09 3700.79,2241.74 3675.59,2216.54 3671.65,2212.6 3629.92,2212.6 3599.73,2212.6 3577.42,2190.29 3577.42,1969.83 3590.55,1956.69 3880.62,1956.69 4227.48,1609.83 4227.48,1494.47 4150.97,1417.96 4089.09,1417.96 4045.19,1374.06 v1(4045.19,1265.77)
PORTD_S17: J2.22 MC1.95 | length 2522.5
  L1-TOP w4.5: v1(4064.98,1510.84) MC1.95@4064.98,1558.68
  L8-BOT w4.5: v1(3685.04,2686.46) 3685.04,2515.75 3682.81,2513.52 3675.79,2506.5 cw(c3672.32,2509.96) 3668.86,2506.5 3654.39,2520.96 ccw(c3650.93,2517.5) 3647.46,2520.96 3637.07,2510.57 ccw(c3640.53,2507.1) 3637.07,2503.64 3670.03,2470.67 cw(c3666.57,2467.21) 3670.03,2463.74 3659.64,2453.35 cw(c3656.17,2456.81) 3652.71,2453.35 3615.82,2490.24 ccw(c3612.35,2486.77) 3608.89,2490.24 3598.49,2479.84 ccw(c3601.96,2476.38) 3598.49,2472.91 3635.38,2436.02 cw(c3631.92,2432.56) 3635.38,2429.09 3624.99,2418.7 cw(c3621.53,2422.16) 3618.06,2418.7 3581.17,2455.59 ccw(c3577.7,2452.13) 3574.24,2455.59 3563.84,2445.2 ccw(c3567.31,2441.73) 3563.84,2438.27 3600.74,2401.37 cw(c3597.27,2397.91) 3600.74,2394.45 3590.34,2384.05 cw(c3586.88,2387.52) 3583.41,2384.05 3546.52,2420.94 ccw(c3543.06,2417.48) 3539.59,2420.94 3529.2,2410.55 ccw(c3532.66,2407.08) 3529.2,2403.62 3566.09,2366.73 cw(c3562.62,2363.26) 3566.09,2359.8 3555.69,2349.4 cw(c3552.23,2352.87) 3548.76,2349.4 3488.16,2410.01 ccw(c3484.7,2406.54) 3481.23,2410.01 3470.84,2399.61 ccw(c3474.3,2396.15) 3470.84,2392.68 3531.44,2332.08 cw(c3527.98,2328.61) 3531.44,2325.15 3521.05,2314.75 cw(c3517.58,2318.22) 3514.12,2314.75 3489.84,2339.03 ccw(c3486.37,2335.57) 3482.91,2339.03 3472.51,2328.64 ccw(c3475.98,2325.17) 3472.51,2321.71 3478.29,2315.93 cw(c3474.83,2312.47) 3478.29,2309 3476.7,2307.41 3476.7,2243.02 3476.7,2223.85 cw(c3471.8,2223.85) 3471.8,2218.95 3446.81,2218.95 ccw(c3446.81,2214.05) 3441.91,2214.05 3441.91,2199.35 ccw(c3446.81,2199.35) 3446.81,2194.45 3471.8,2194.45 cw(c3471.8,2189.55) 3476.7,2189.55 3476.7,2187.3 3476.7,1916.06 3826.77,1565.99 3826.77,1488.99 3837.51,1478.25 3955.5,1478.25 3963.72,1486.47 3963.72,1519.66 3998.12,1554.06 4042.58,1554.06 4064.98,1531.66 v1(4064.98,1510.84)
PORTD_S18: J2.23 MC1.105 | length 2522.6
  L1-TOP w4.5: v1(4163.4,1469.5) MC1.105@4163.4,1558.68
  L8-BOT w4.5: v1(3653.54,2825.35) 3653.54,2812.48 3780.38,2685.64 3780.38,2431.77 3780.38,2425.03 3821.94,2383.48 3821.94,2350.39 3810.88,2339.33 3709.7,2339.33 3684.29,2313.92 3684.29,2248.57 3664.6,2228.89 3660.88,2228.89 3660.67,2229.1 3592.89,2229.1 3560.96,2197.16 3560.82,2197.16 3560.82,1950.83 3643.54,1868.11 3660.08,1868.11 3764.11,1868.11 cw(c3764.11,1863.21) 3769.01,1863.21 ccw(c3773.91,1863.21) 3773.91,1858.31 3788.61,1858.31 ccw(c3788.61,1863.21) 3793.51,1863.21 3793.51,1886.2 cw(c3798.41,1886.2) 3798.41,1891.1 3813.11,1891.1 cw(c3813.11,1886.2) 3818.01,1886.2 3818.01,1848.01 ccw(c3822.91,1848.01) 3822.91,1843.11 3837.61,1843.11 ccw(c3837.61,1848.01) 3842.51,1848.01 3842.51,1888.21 cw(c3847.41,1888.21) 3847.41,1893.11 3862.11,1893.11 cw(c3862.11,1888.21) 3867.01,1888.21 3867.01,1848.01 ccw(c3871.91,1848.01) 3871.91,1843.11 3886.61,1843.11 ccw(c3886.61,1848.01) 3891.51,1848.01 3891.51,1863.21 cw(c3896.41,1863.21) 3896.41,1868.11 3898.66,1868.11 3939.48,1868.11 4163.4,1644.19 4163.4,1631.75 4163.4,1606.11 ccw(c4168.3,1606.11) 4168.3,1601.21 4208.88,1601.21 cw(c4208.88,1596.31) 4213.78,1596.31 4213.78,1581.61 cw(c4208.88,1581.61) 4208.88,1576.71 4168.28,1576.71 ccw(c4168.28,1571.81) 4163.38,1571.81 4163.38,1557.11 ccw(c4168.28,1557.11) 4168.28,1552.21 4208.88,1552.21 cw(c4208.88,1547.31) 4213.78,1547.31 4213.78,1532.61 cw(c4208.88,1532.61) 4208.88,1527.71 4168.3,1527.71 ccw(c4168.3,1522.81) 4163.4,1522.81 4163.4,1496.06 v1(4163.4,1469.5)
PORTD_S19: J2.24 MC1.93 | length 2523.1
  L1-TOP w4.5: v1(4045.29,1469.5) MC1.93@4045.29,1558.68
  L8-BOT w4.5: v1(3653.54,2599.75) 3653.54,2563.6 3642.1,2552.17 3524.96,2435.03 3387.02,2435.03 3386.36,2434.37 3377.02,2425.03 3377.02,2422.55 ccw(c3381.92,2422.55) 3381.92,2417.65 3446.02,2417.65 cw(c3446.02,2412.75) 3450.92,2412.75 3450.92,2398.05 cw(c3446.02,2398.05) 3446.02,2393.15 3381.92,2393.15 ccw(c3381.92,2388.25) 3377.02,2388.25 3377.02,2373.55 ccw(c3381.92,2373.55) 3381.92,2368.65 3449.94,2368.65 cw(c3449.94,2363.75) 3454.84,2363.75 3454.84,2349.05 cw(c3449.94,2349.05) 3449.94,2344.15 3381.92,2344.15 ccw(c3381.92,2339.25) 3377.02,2339.25 3377.02,2324.55 ccw(c3381.92,2324.55) 3381.92,2319.65 3449.94,2319.65 cw(c3449.94,2314.75) 3454.84,2314.75 3454.84,2300.05 cw(c3449.94,2300.05) 3449.94,2295.15 3381.92,2295.15 ccw(c3381.92,2290.25) 3377.02,2290.25 3377.02,2275.55 ccw(c3381.92,2275.55) 3381.92,2270.65 3449.94,2270.65 cw(c3449.94,2265.75) 3454.84,2265.75 3454.84,2251.05 cw(c3449.94,2251.05) 3449.94,2246.15 3381.92,2246.15 ccw(c3381.92,2241.25) 3377.02,2241.25 3377.02,2236 3396.07,2216.95 3460.1,2152.92 3460.1,1909.11 3811.02,1558.19 3811.02,1474.98 3827.39,1458.61 3967.31,1458.61 3983.7,1475 3983.7,1510.84 4007.84,1534.98 ; 4008.61,1534.98 4007.84,1534.98 ; v1(4045.29,1469.5) 4045.29,1523.22 4033.52,1534.98 4007.84,1534.98
PORTD_S20: J2.25 MC1.103 | length 2522.5
  L1-TOP w4.5: v1(4143.72,1510.84) MC1.103@4143.72,1558.68
  L8-BOT w4.5: v1(3622.04,2912.06) 3622.04,2832.67 3608.1,2818.73 3608.1,2798.39 3626.97,2779.53 3668.51,2779.53 3763.78,2684.26 3763.78,2423.46 3594.98,2254.66 3594.83,2254.66 3544.22,2204.04 3544.22,1943.02 3648.81,1838.43 3660.08,1838.43 3673.21,1851.55 3701.83,1851.55 3786.65,1766.73 3800.98,1766.73 ccw(c3800.98,1771.63) 3805.88,1771.63 cw(c3810.78,1771.63) 3810.78,1776.53 3825.48,1776.53 cw(c3825.48,1771.63) 3830.38,1771.63 3830.38,1732.87 ccw(c3835.28,1732.87) 3835.28,1727.97 3849.98,1727.97 ccw(c3849.98,1732.87) 3854.88,1732.87 3854.88,1786.83 cw(c3859.78,1786.83) 3859.78,1791.73 3874.48,1791.73 cw(c3874.48,1786.83) 3879.38,1786.83 3879.38,1730.27 ccw(c3884.28,1730.27) 3884.28,1725.37 3898.98,1725.37 ccw(c3898.98,1730.27) 3903.88,1730.27 3903.88,1786.83 cw(c3908.78,1786.83) 3908.78,1791.73 3923.48,1791.73 cw(c3923.48,1786.83) 3928.38,1786.83 3928.38,1730.27 ccw(c3933.28,1730.27) 3933.28,1725.37 3947.98,1725.37 ccw(c3947.98,1730.27) 3952.88,1730.27 3952.88,1786.83 cw(c3957.78,1786.83) 3957.78,1791.73 3972.48,1791.73 cw(c3972.48,1786.83) 3977.38,1786.83 3977.38,1730.27 ccw(c3982.28,1730.27) 3982.28,1725.37 3996.98,1725.37 ccw(c3996.98,1730.27) 4001.88,1730.27 4001.88,1761.83 cw(c4006.78,1761.83) 4006.78,1766.73 4009.03,1766.73 4012.8,1766.73 4143.72,1635.81 v1(4143.72,1510.84)
PORTD_S21: J2.26 MC1.91 | length 2522.5
  L1-TOP w4.5: v1(4025.61,1510.84) MC1.91@4025.61,1558.68
  L8-BOT w4.5: v1(3622.04,2686.46) 3622.04,2596.13 3613.19,2587.28 3613.19,2548.49 3566.38,2501.68 3541.12,2501.68 3523.57,2501.68 ccw(c3523.57,2496.78) 3518.67,2496.78 3518.67,2470.57 cw(c3513.77,2470.57) 3513.77,2465.67 3499.07,2465.67 cw(c3499.07,2470.57) 3494.17,2470.57 3494.17,2496.78 ccw(c3489.27,2496.78) 3489.27,2501.68 3474.57,2501.68 ccw(c3474.57,2496.78) 3469.67,2496.78 3469.67,2458.06 cw(c3464.77,2458.06) 3464.77,2453.16 3450.07,2453.16 cw(c3450.07,2458.06) 3445.17,2458.06 3445.17,2496.78 ccw(c3440.27,2496.78) 3440.27,2501.68 3425.57,2501.68 ccw(c3425.57,2496.78) 3420.67,2496.78 3420.67,2458.06 cw(c3415.77,2458.06) 3415.77,2453.16 3401.07,2453.16 cw(c3401.07,2458.06) 3396.17,2458.06 3396.17,2496.78 ccw(c3391.27,2496.78) 3391.27,2501.68 3376.57,2501.68 ccw(c3376.57,2496.78) 3371.67,2496.78 3371.67,2458.06 cw(c3366.77,2458.06) 3366.77,2453.16 3352.07,2453.16 cw(c3352.07,2458.06) 3347.17,2458.06 3347.17,2496.78 ccw(c3342.27,2496.78) 3342.27,2501.68 3315.52,2501.68 3287.76,2501.68 3279.53,2493.45 3279.53,2483.39 3360.52,2402.39 3360.52,2229.16 3443.5,2146.19 3443.5,1902.24 3790.98,1554.76 3790.98,1426.02 3810.32,1406.67 3892.39,1406.67 3921.11,1377.95 3992.13,1377.95 4007.87,1393.7 4007.87,1493.11 v1(4025.61,1510.84)
PORTD_S22: J2.27 MC1.101 | length 2522.5
  L1-TOP w4.5: v1(4124.03,1469.5) MC1.101@4124.03,1558.68
  L8-BOT w4.5: v1(3590.54,2825.35) 3590.54,2797.09 3648.14,2739.49 3692.49,2739.49 3746.06,2685.92 3746.06,2430.8 3587.64,2272.37 3587.5,2272.37 3526.5,2211.38 3526.5,1937.4 3641.98,1821.93 3666.92,1821.93 3680.04,1835.05 3694.99,1835.05 3828.74,1701.31 3828.74,1687 3819.79,1678.06 3819.79,1668.23 3834.48,1653.54 3848.01,1653.54 3862.82,1653.54 ccw(c3862.82,1658.44) 3867.72,1658.44 3867.72,1696.76 cw(c3872.62,1696.76) 3872.62,1701.66 3887.32,1701.66 cw(c3887.32,1696.76) 3892.22,1696.76 3892.22,1655.26 ccw(c3897.12,1655.26) 3897.12,1650.36 3911.82,1650.36 ccw(c3911.82,1655.26) 3916.72,1655.26 3916.72,1701.59 cw(c3921.62,1701.59) 3921.62,1706.49 3936.32,1706.49 cw(c3936.32,1701.59) 3941.22,1701.59 3941.22,1655.26 ccw(c3946.12,1655.26) 3946.12,1650.36 3960.82,1650.36 ccw(c3960.82,1655.26) 3965.72,1655.26 3965.72,1701.59 cw(c3970.62,1701.59) 3970.62,1706.49 3985.32,1706.49 cw(c3985.32,1701.59) 3990.22,1701.59 3990.22,1655.26 ccw(c3995.12,1655.26) 3995.12,1650.36 4009.82,1650.36 ccw(c4009.82,1655.26) 4014.72,1655.26 4014.72,1701.59 cw(c4019.62,1701.59) 4019.62,1706.49 4034.32,1706.49 cw(c4034.32,1701.59) 4039.22,1701.59 4039.22,1638.76 ccw(c4044.12,1638.76) 4044.12,1633.86 4058.82,1633.86 ccw(c4058.82,1638.76) 4063.72,1638.76 4063.72,1648.64 cw(c4068.62,1648.64) 4068.62,1653.54 4070.87,1653.54 4102.48,1653.54 4124.03,1631.99 v1(4124.03,1469.5)
PORTD_S23: J2.28 MC1.92 | length 2522.7
  L1-TOP w4.5: v1(4025.38,1225.65) 4025.54,1225.82 4025.54,1315.3 MC1.92@4025.71,1315.47
  L8-BOT w4.5: v1(3590.54,2599.75) 3590.54,2549.17 3566.16,2524.79 3544.19,2524.79 3537.58,2518.18 3254.96,2518.18 3246.56,2509.79 3246.56,2493.02 3344.02,2395.56 3344.02,2222.33 3348.07,2218.29 3426.8,2139.55 3426.8,2094.49 3426.9,2094.39 3426.9,1888.09 3744.09,1570.9 3744.09,1543.31 3744.09,1528.18 ccw(c3748.99,1528.18) 3748.99,1523.28 3764.19,1523.28 cw(c3764.19,1518.38) 3769.09,1518.38 3769.09,1503.68 cw(c3764.19,1503.68) 3764.19,1498.78 3723.99,1498.78 ccw(c3723.99,1493.88) 3719.09,1493.88 3719.09,1479.18 ccw(c3723.99,1479.18) 3723.99,1474.28 3764.19,1474.28 cw(c3764.19,1469.38) 3769.09,1469.38 3769.09,1454.68 cw(c3764.19,1454.68) 3764.19,1449.78 3744.65,1449.78 ccw(c3744.65,1444.88) 3739.75,1444.88 3739.75,1430.18 ccw(c3744.65,1430.18) 3744.65,1425.28 3764.19,1425.28 cw(c3764.19,1420.38) 3769.09,1420.38 3769.09,1405.68 cw(c3764.19,1405.68) 3764.19,1400.78 3723.99,1400.78 ccw(c3723.99,1395.88) 3719.09,1395.88 3719.09,1381.18 ccw(c3723.99,1381.18) 3723.99,1376.28 3739.19,1376.28 cw(c3739.19,1371.38) 3744.09,1371.38 3744.09,1369.13 3744.09,1363 3753.87,1353.23 3764.73,1353.23 3777.62,1353.23 ccw(c3777.62,1358.13) 3782.52,1358.13 3782.52,1379.99 cw(c3787.42,1379.99) 3787.42,1384.89 3802.12,1384.89 cw(c3802.12,1379.99) 3807.02,1379.99 3807.02,1358.13 ccw(c3811.92,1358.13) 3811.92,1353.23 3838.67,1353.23 3977.48,1353.23 4025.38,1305.33 v1(4025.38,1225.65)
PORTD_S24: J2.29 MC1.99 | length 2522.5
  L1-TOP w4.5: v1(4104.35,1510.84) MC1.99@4104.35,1558.68
  L8-BOT w4.5: v1(3559.04,2912.06) 3559.04,2857.73 3552.69,2851.38 3552.69,2784.95 3608.41,2729.23 3684.61,2729.23 3725.39,2688.45 3725.39,2433.6 3722.63,2430.85 3709.48,2417.69 cw(c3706.02,2421.16) 3702.55,2417.69 3693.31,2426.94 ccw(c3689.84,2423.47) 3686.38,2426.94 3675.98,2416.55 ccw(c3679.45,2413.08) 3675.98,2409.62 3685.23,2400.37 cw(c3681.76,2396.9) 3685.23,2393.44 3683.64,2391.85 3580.76,2288.97 3580.62,2288.97 3509.9,2218.25 3509.9,1929.74 3621.15,1818.49 3622.74,1816.9 3650.52,1789.12 ccw(c3653.98,1792.59) 3657.45,1789.12 3673.15,1804.82 cw(c3676.62,1801.36) 3680.08,1804.82 3690.47,1794.43 cw(c3687.01,1790.96) 3690.47,1787.5 3673.38,1770.4 ccw(c3676.84,1766.94) 3673.38,1763.47 3683.77,1753.08 ccw(c3687.24,1756.54) 3690.7,1753.08 3715.73,1778.1 cw(c3719.19,1774.64) 3722.66,1778.1 3733.05,1767.71 cw(c3729.59,1764.24) 3733.05,1760.78 3708.03,1735.75 ccw(c3711.49,1732.29) 3708.03,1728.82 3718.42,1718.43 ccw(c3721.88,1721.89) 3725.35,1718.43 3750.37,1743.45 cw(c3753.84,1739.99) 3757.3,1743.45 3767.7,1733.06 cw(c3764.23,1729.59) 3767.7,1726.13 3742.67,1701.11 ccw(c3746.14,1697.64) 3742.67,1694.18 3753.07,1683.78 ccw(c3756.53,1687.25) 3760,1683.78 3785.02,1708.81 cw(c3788.49,1705.34) 3791.95,1708.81 3802.35,1698.41 cw(c3798.88,1694.95) 3802.35,1691.48 3778.72,1667.85 ccw(c3782.18,1664.39) 3778.72,1660.92 3796.04,1643.6 3797.63,1642.01 3827.1,1612.54 3832.73,1612.54 3843.71,1612.54 ccw(c3843.71,1617.44) 3848.61,1617.44 3848.61,1628.96 cw(c3853.51,1628.96) 3853.51,1633.86 3868.21,1633.86 cw(c3868.21,1628.96) 3873.11,1628.96 3873.11,1616.35 ccw(c3878.01,1616.35) 3878.01,1611.45 3892.71,1611.45 ccw(c3892.71,1616.35) 3897.61,1616.35 3897.61,1628.96 cw(c3902.51,1628.96) 3902.51,1633.86 3917.21,1633.86 cw(c3917.21,1628.96) 3922.11,1628.96 3922.11,1616.35 ccw(c3927.01,1616.35) 3927.01,1611.45 3941.71,1611.45 ccw(c3941.71,1616.35) 3946.61,1616.35 3946.61,1628.96 cw(c3951.51,1628.96) 3951.51,1633.86 3966.21,1633.86 cw(c3966.21,1628.96) 3971.11,1628.96 3971.11,1616.35 ccw(c3976.01,1616.35) 3976.01,1611.45 3990.71,1611.45 ccw(c3990.71,1616.35) 3995.61,1616.35 3995.61,1628.96 cw(c4000.51,1628.96) 4000.51,1633.86 4015.21,1633.86 cw(c4015.21,1628.96) 4020.11,1628.96 4020.11,1617.44 ccw(c4025.01,1617.44) 4025.01,1612.54 4051.76,1612.54 4060.69,1612.54 4104.35,1568.88 v1(4104.35,1510.84)
PORTD_S25: J2.30 MC1.90 | length 2522.7
  L1-TOP w4.5: v1(4005.82,1265.77) 4005.92,1265.87 MC1.90@4005.92,1315.37 MC1.90@4006.02,1315.47
  L8-BOT w4.5: v1(3559.04,2686.46) 3559.04,2596.13 3548.23,2585.32 3548.23,2552.17 3530.74,2534.68 3243.91,2534.68 3229.45,2520.22 3229.45,2486.8 3327.52,2388.72 3327.52,2215.5 3336.44,2206.58 3410.3,2132.72 3410.3,1875.78 3716.08,1570 3716.08,1515.29 3665.35,1464.57 3665.35,1448.82 3665.35,1429.25 ccw(c3670.25,1429.25) 3670.25,1424.35 3699.65,1424.35 cw(c3699.65,1419.45) 3704.55,1419.45 3704.55,1404.75 cw(c3699.65,1404.75) 3699.65,1399.85 3595.86,1399.85 ccw(c3595.86,1394.95) 3590.96,1394.95 3590.96,1380.25 ccw(c3595.86,1380.25) 3595.86,1375.35 3660.45,1375.35 cw(c3660.45,1370.45) 3665.35,1370.45 3665.35,1368.2 3665.35,1356.33 3687.39,1334.29 3976.73,1334.29 4005.82,1305.2 v1(4005.82,1265.77)
PORTD_S26: J2.31 MC1.97 | length 2522.5
  L1-TOP w4.5: v1(4084.66,1469.5) MC1.97@4084.66,1558.68
  L8-BOT w4.5: v1(3527.54,2825.35) 3527.54,2747.07 3556.06,2718.54 3677.13,2718.54 3707.68,2687.99 3707.68,2471.58 3645.84,2409.74 3645.84,2377.53 3634.13,2365.81 cw(c3630.66,2369.28) 3627.2,2365.81 3624.46,2368.55 ccw(c3621,2365.08) 3617.53,2368.55 3607.14,2358.15 ccw(c3610.6,2354.69) 3607.14,2351.22 3609.94,2348.42 cw(c3606.48,2344.95) 3609.94,2341.49 3599.55,2331.09 cw(c3596.08,2334.56) 3592.62,2331.09 3581.73,2341.98 ccw(c3578.26,2338.52) 3574.8,2341.98 3564.4,2331.59 ccw(c3567.87,2328.12) 3564.4,2324.66 3575.22,2313.84 cw(c3571.76,2310.38) 3575.22,2306.91 3564.83,2296.52 cw(c3561.36,2299.98) 3557.9,2296.52 3547.08,2307.34 ccw(c3543.62,2303.87) 3540.15,2307.34 3529.76,2296.94 ccw(c3533.22,2293.48) 3529.76,2290.01 3540.58,2279.19 cw(c3537.11,2275.73) 3540.58,2272.26 3530.18,2261.87 cw(c3526.72,2265.33) 3523.25,2261.87 3513.99,2271.13 ccw(c3510.52,2267.66) 3507.06,2271.13 3496.67,2260.73 ccw(c3500.13,2257.27) 3496.67,2253.81 3505.86,2244.61 cw(c3502.39,2241.15) 3505.86,2237.68 3504.27,2236.09 3493.3,2225.13 3493.3,1923 3845.44,1570.87 3849.1,1570.87 3862.41,1570.87 cw(c3862.41,1565.97) 3867.31,1565.97 3867.31,1500.67 ccw(c3872.21,1500.67) 3872.21,1495.77 3886.91,1495.77 ccw(c3886.91,1500.67) 3891.81,1500.67 3891.81,1590.97 cw(c3896.71,1590.97) 3896.71,1595.87 3911.41,1595.87 cw(c3911.41,1590.97) 3916.31,1590.97 3916.31,1500.67 ccw(c3921.21,1500.67) 3921.21,1495.77 3935.91,1495.77 ccw(c3935.91,1500.67) 3940.81,1500.67 3940.81,1565.97 cw(c3945.71,1565.97) 3945.71,1570.87 3947.96,1570.87 4058.24,1570.87 4084.66,1544.45 v1(4084.66,1469.5)
PORTD_S27: J2.32 MC1.88 | length 2522.7
  L1-TOP w4.5: v1(3986.01,1225.65) 3986.17,1225.82 3986.17,1315.3 MC1.88@3986.34,1315.47
  L8-BOT w4.5: v1(3527.54,2599.75) 3527.54,2562.97 3515.75,2551.18 3234.65,2551.18 3212.95,2529.49 3212.95,2479.96 3311.02,2381.89 3311.02,2208.66 3393.7,2125.98 3393.7,1866.14 3696.85,1562.99 3696.85,1523.62 3645.67,1472.44 3586.61,1472.44 3566.93,1452.76 3566.93,1334.65 3586.61,1314.96 3596.45,1314.96 3612.18,1314.96 ccw(c3612.18,1319.86) 3617.08,1319.86 3617.08,1331.93 cw(c3621.98,1331.93) 3621.98,1336.83 3636.68,1336.83 cw(c3636.68,1331.93) 3641.58,1331.93 3641.58,1294.86 ccw(c3646.48,1294.86) 3646.48,1289.96 3661.18,1289.96 ccw(c3661.18,1294.86) 3666.08,1294.86 3666.08,1310.06 cw(c3670.98,1310.06) 3670.98,1314.96 3673.23,1314.96 3962.38,1314.96 3986.01,1291.34 v1(3986.01,1225.65)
